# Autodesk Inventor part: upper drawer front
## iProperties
Created: 2005-05
Part Number: upper drawer front
Material: mdf
Document SubType Name: Modeling
Designer: a.campbell
Manufacturer: Standard
Standards Organization: Custom
length: 278
thickness: 12
width: 109
Author: a.campbell
Comments: machine to detail
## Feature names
1. Extrusion1
2. Extrusion2
